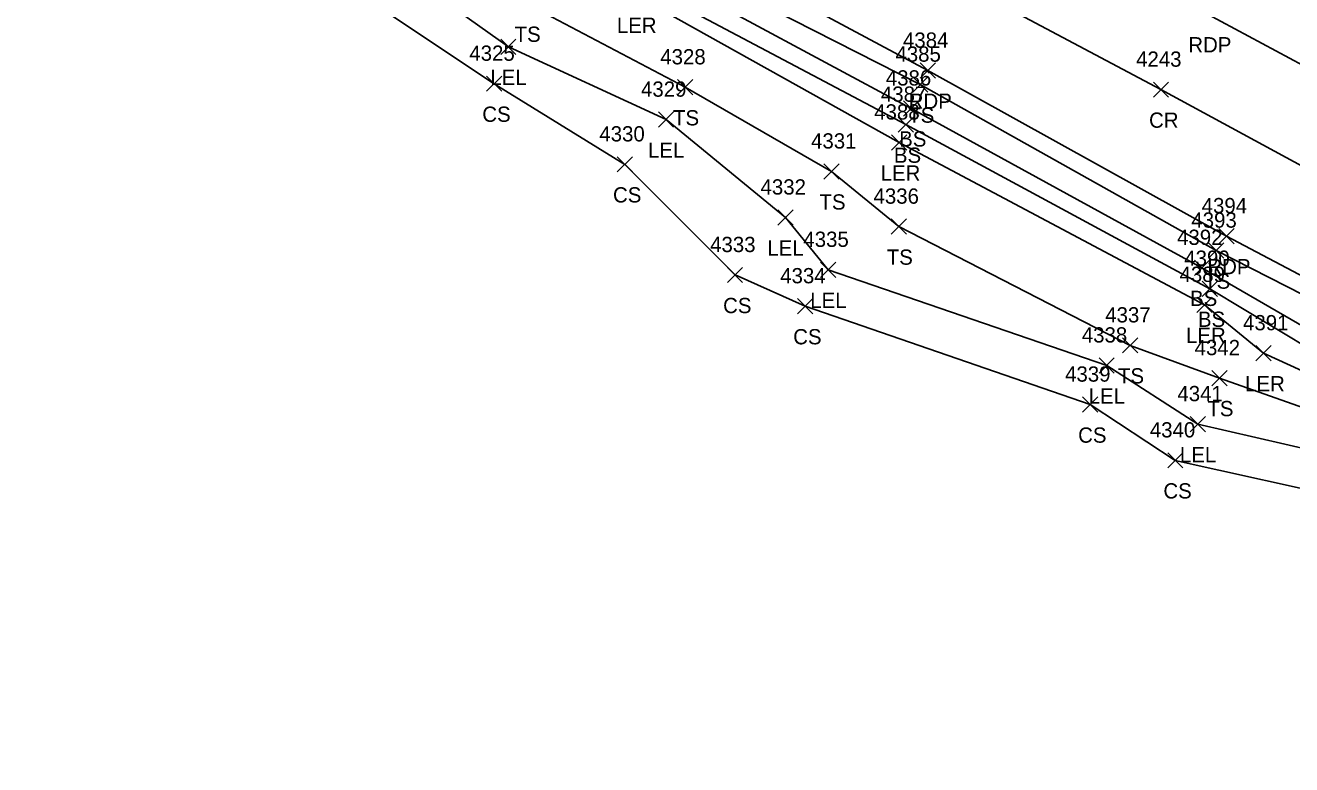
# Model space of a CAD drawing. Extents: x 1462089 to 1464015, y 730534 to 736144.
# Drawn here: x 1462373.7 to 1462539.6, y 731943.3 to 732040.2 of the extents above; entities that cross this region are included whole.
import ezdxf

# ---------------------------------------------------------------- set-up
doc = ezdxf.new("R2010")
doc.units = 0
for name, color, linetype in [('L_A', 7, 'Continuous'), ('L_I', 7, 'Continuous'), ('L_TIC', 7, 'Continuous'), ('LARO', 7, 'Continuous'), ('LELB', 7, 'Continuous'), ('P_A', 7, 'Continuous'), ('P_I', 7, 'Continuous'), ('P_TIC', 7, 'Continuous'), ('PET', 7, 'Continuous'), ('PRC', 7, 'Continuous')]:
    doc.layers.add(name, color=color, linetype=linetype)

msp = doc.modelspace()

# ---------------------------------------------------------------- linework, layer by layer
at = {"layer": 'L_TIC'}
for points in [[(1462435.98, 732036.36), (1462437.98, 732038.36)], [(1462437.98, 732036.36), (1462435.98, 732038.36)], [(1462434.13, 732031.54), (1462436.13, 732033.54)], [(1462436.13, 732031.54), (1462434.13, 732033.54)], [(1462459.14, 732031.07), (1462461.14, 732033.07)], [(1462461.14, 732031.07), (1462459.14, 732033.07)], [(1462489.94, 732031.42), (1462491.94, 732033.42)], [(1462491.94, 732031.42), (1462489.94, 732033.42)], [(1462488.73, 732028.3), (1462490.73, 732030.3)], [(1462490.73, 732028.3), (1462488.73, 732030.3)], [(1462456.63, 732026.83), (1462458.63, 732028.83)], [(1462458.63, 732026.83), (1462456.63, 732028.83)], [(1462488.04, 732026.17), (1462490.04, 732028.17)], [(1462490.04, 732026.17), (1462488.04, 732028.17)], [(1462487.16, 732023.84), (1462489.16, 732025.84)], [(1462489.16, 732023.84), (1462487.16, 732025.84)], [(1462451.25, 732020.97), (1462453.25, 732022.97)], [(1462453.25, 732020.97), (1462451.25, 732022.97)], [(1462478.32, 732020.04), (1462480.32, 732022.04)], [(1462480.32, 732020.04), (1462478.32, 732022.04)], [(1462472.27, 732014.01), (1462474.27, 732016.01)], [(1462474.27, 732014.01), (1462472.27, 732016.01)], [(1462487.13, 732012.81), (1462489.13, 732014.81)], [(1462489.13, 732012.81), (1462487.13, 732014.81)], [(1462528.7, 732009.67), (1462530.7, 732011.67)], [(1462530.7, 732009.67), (1462528.7, 732011.67)], [(1462465.67, 732006.47), (1462467.67, 732008.47)], [(1462467.67, 732006.47), (1462465.67, 732008.47)], [(1462477.88, 732007.15), (1462479.88, 732009.15)], [(1462479.88, 732007.15), (1462477.88, 732009.15)], [(1462526.83, 732007.41), (1462528.83, 732009.41)], [(1462528.83, 732007.41), (1462526.83, 732009.41)], [(1462527.86, 732004.67), (1462529.86, 732006.67)], [(1462529.86, 732004.67), (1462527.86, 732006.67)], [(1462474.85, 732002.38), (1462476.85, 732004.38)], [(1462476.85, 732002.38), (1462474.85, 732004.38)], [(1462527.16, 732002.56), (1462529.16, 732004.56)], [(1462529.16, 732002.56), (1462527.16, 732004.56)], [(1462517.42, 731997.25), (1462519.42, 731999.25)], [(1462519.42, 731997.25), (1462517.42, 731999.25)], [(1462534.9, 731996.22), (1462536.9, 731998.22)], [(1462536.9, 731996.22), (1462534.9, 731998.22)], [(1462514.35, 731994.62), (1462516.35, 731996.62)], [(1462516.35, 731994.62), (1462514.35, 731996.62)], [(1462529.13, 731992.96), (1462531.13, 731994.96)], [(1462531.13, 731992.96), (1462529.13, 731994.96)], [(1462512.17, 731989.49), (1462514.17, 731991.49)], [(1462514.17, 731989.49), (1462512.17, 731991.49)], [(1462526.3, 731986.93), (1462528.3, 731988.93)], [(1462528.3, 731986.93), (1462526.3, 731988.93)], [(1462523.34, 731982.18), (1462525.34, 731984.18)], [(1462525.34, 731982.18), (1462523.34, 731984.18)]]:
    msp.add_lwpolyline(points, dxfattribs=at)
at = {"layer": 'LARO'}
for points in [[(1462264.53, 732141.37), (1462280.8, 732137.45), (1462304.56, 732121.88), (1462332.73, 732110.49), (1462351.01, 732098.25), (1462390.86, 732077.94), (1462401.62, 732073.62), (1462407.64, 732069.31), (1462436.18, 732056.01), (1462453.6, 732044.2), (1462488.16, 732024.84), (1462528.16, 732003.56), (1462535.9, 731997.22), (1462564.82, 731983.98), (1462588.79, 731971.39), (1462609.63, 731960.71), (1462616, 731952.79), (1462625.86, 731949.03), (1462651.51, 731937.11), (1462666.81, 731928.04), (1462675.53, 731921.26)], [(1462254.75, 732128.31), (1462262.86, 732125.81), (1462285.58, 732115.58), (1462314.64, 732100.45), (1462332.44, 732090.84), (1462352.68, 732082.74), (1462381.15, 732067.23), (1462394.72, 732062.92), (1462415.67, 732052.59), (1462436.98, 732037.36), (1462457.63, 732027.83), (1462473.27, 732015.01), (1462478.88, 732008.15), (1462515.35, 731995.62), (1462527.3, 731987.93), (1462550.08, 731982.66), (1462558.92, 731973.67), (1462570.85, 731962.61), (1462577.22, 731952.72), (1462589.81, 731946.27), (1462608.55, 731942.12)]]:
    msp.add_lwpolyline(points, dxfattribs=at)
at = {"layer": 'LELB'}
for points in [[(1462268.94, 732149.28), (1462308.43, 732128.71), (1462354.33, 732103.89), (1462394.15, 732084.39), (1462412.36, 732075.22), (1462457.64, 732049.36), (1462490.94, 732032.42), (1462529.7, 732010.67), (1462568.83, 731990.73), (1462593.62, 731976.79), (1462623.59, 731960), (1462654.37, 731942.73), (1462672.05, 731932.37), (1462692.12, 731920.93), (1462699.46, 731912.9)], [(1462266.76, 732145.23), (1462282.11, 732139.32), (1462308.3, 732126.23), (1462353.11, 732101.19), (1462392.77, 732082.13), (1462410, 732072.54), (1462437.81, 732058.16), (1462456.1, 732047.42), (1462489.73, 732029.3), (1462527.83, 732008.41), (1462565.4, 731986.64), (1462591.35, 731974.35), (1462620.09, 731957.41), (1462653.18, 731940.63), (1462669.35, 731930.26), (1462687.58, 731918.81), (1462686.57, 731917.12)], [(1462265.41, 732143.18), (1462280.8, 732137.45), (1462306.42, 732125.03), (1462332.73, 732110.49), (1462352.67, 732099.71), (1462392.05, 732079.23), (1462401.62, 732073.62), (1462408.5, 732070.13), (1462436.18, 732056.01), (1462454.76, 732045.38), (1462489.04, 732027.17), (1462528.86, 732005.67), (1462564.82, 731983.98), (1462590.19, 731972.53), (1462609.63, 731960.71), (1462619.8, 731955.25), (1462652.26, 731939.11), (1462668.15, 731929.16), (1462686.57, 731917.12)], [(1462259.38, 732133.38), (1462264.6, 732131.81), (1462288.8, 732120.32), (1462319.43, 732102.58), (1462334.48, 732096.72), (1462355.6, 732085.94), (1462385.9, 732070.37), (1462398.62, 732070.04), (1462418.37, 732059.41), (1462439.39, 732043.02), (1462460.14, 732032.07), (1462479.32, 732021.04), (1462488.13, 732013.81), (1462518.42, 731998.25), (1462530.13, 731993.96), (1462552.89, 731985.91), (1462561.32, 731977.65), (1462577.83, 731967.62), (1462595.47, 731955.47), (1462607.49, 731949.55), (1462608.2, 731946.49), (1462648.04, 731929.15)], [(1462251.41, 732121.51), (1462260.34, 732120.37), (1462283.18, 732109.04), (1462310.5, 732093.66), (1462326.84, 732085.72), (1462347.54, 732077.16), (1462380.03, 732062.41), (1462392.14, 732057.7), (1462410.67, 732048.85), (1462435.13, 732032.54), (1462452.25, 732021.97), (1462466.67, 732007.47), (1462475.85, 732003.38), (1462513.17, 731990.49), (1462524.34, 731983.18), (1462547.61, 731978.02), (1462566.75, 731959.76), (1462577.22, 731952.72), (1462603.04, 731935.03)]]:
    msp.add_lwpolyline(points, dxfattribs=at)
at = {"layer": 'P_TIC'}
for points in [[(1462490.93, 732033.25), (1462492.93, 732035.25)], [(1462492.93, 732033.25), (1462490.93, 732035.25)], [(1462521.46, 732030.76), (1462523.46, 732032.76)], [(1462523.46, 732030.76), (1462521.46, 732032.76)], [(1462530.05, 732011.56), (1462532.05, 732013.56)], [(1462532.05, 732011.56), (1462530.05, 732013.56)]]:
    msp.add_lwpolyline(points, dxfattribs=at)
at = {"layer": 'PET'}
for points in [[(1462744.84, 731999.27), (1462742.33, 731993.22), (1462735.48, 731981.56), (1462730.64, 731976.02), (1462728.98, 731974.4), (1462721.4, 731968.23), (1462710.52, 731963.39), (1462695.09, 731960.11), (1462681.48, 731960.8), (1462668.27, 731966.22), (1462638.36, 731982.5), (1462604.11, 732001.12), (1462569.71, 732019.56), (1462528.56, 732041.64), (1462492.34, 732061.31), (1462453.18, 732082.82), (1462423.34, 732099.23), (1462387.22, 732118.93), (1462352.22, 732137.53), (1462321.66, 732153.59), (1462281.35, 732173.27)], [(1462270.45, 732152.1), (1462310.22, 732132.27), (1462357.01, 732107.8), (1462395.93, 732087.15), (1462413.05, 732077.52), (1462458.62, 732052.14), (1462491.93, 732034.25), (1462531.05, 732012.56), (1462569.66, 731992.17), (1462594.88, 731978.54), (1462624.97, 731962.02), (1462656.05, 731945.2), (1462673.71, 731935.25), (1462698.16, 731921.06), (1462701.54, 731917.94), (1462703.76, 731916.18), (1462713.41, 731906.91), (1462715.89, 731903.55), (1462716.95, 731899.27), (1462716.13, 731895.69)]]:
    msp.add_lwpolyline(points, dxfattribs=at)
at = {"layer": 'PRC'}
msp.add_lwpolyline([(1462724.35, 731923.62), (1462700.47, 731936.6), (1462662.88, 731956.21), (1462633.35, 731971.36), (1462598.49, 731991.21), (1462563, 732009.78), (1462522.46, 732031.76), (1462486.74, 732050.76), (1462447.61, 732072.43), (1462416.62, 732089.42), (1462381.13, 732108.67), (1462345.7, 732127.48), (1462314.56, 732143.61), (1462276.11, 732162.81)], dxfattribs=at)

# ---------------------------------------------------------------- texts
at = {"layer": 'L_A'}
for s, p in [('LER', (1462451.19, 732039.2)), ('TS', (1462437.8, 732038.02)), ('LEL', (1462434.62, 732032.36)), ('CS', (1462433.57, 732027.54)), ('TS', (1462458.55, 732027.07)), ('TS', (1462489.35, 732027.42)), ('BS', (1462488.17, 732024.3)), ('LEL', (1462455.27, 732022.83)), ('BS', (1462487.48, 732022.17)), ('LER', (1462485.74, 732019.84)), ('CS', (1462450.69, 732016.97)), ('TS', (1462477.73, 732016.04)), ('LEL', (1462470.91, 732010.01)), ('TS', (1462486.54, 732008.81)), ('TS', (1462528.11, 732005.67)), ('LEL', (1462476.52, 732003.15)), ('BS', (1462526.27, 732003.41)), ('CS', (1462465.11, 732002.47)), ('BS', (1462527.3, 732000.67)), ('CS', (1462474.29, 731998.38)), ('LER', (1462525.74, 731998.56)), ('TS', (1462516.83, 731993.25)), ('LER', (1462533.48, 731992.22)), ('LEL', (1462512.99, 731990.62)), ('TS', (1462528.54, 731988.96)), ('CS', (1462511.61, 731985.49)), ('LEL', (1462524.94, 731982.93)), ('CS', (1462522.78, 731978.18))]:
    msp.add_text(s, height=2, dxfattribs=at).set_placement(p)
at = {"layer": 'L_I'}
for s, p in [('4325', (1462431.87, 732035.54)), ('4328', (1462456.88, 732035.07)), ('4385', (1462487.68, 732035.42)), ('4329', (1462454.36, 732030.83)), ('4386', (1462486.42, 732032.3)), ('4387', (1462485.78, 732030.17)), ('4388', (1462484.9, 732027.84)), ('4330', (1462448.9, 732024.97)), ('4331', (1462476.63, 732024.04)), ('4332', (1462470.01, 732018.01)), ('4336', (1462484.81, 732016.81)), ('4393', (1462526.44, 732013.67)), ('4335', (1462475.62, 732011.15)), ('4392', (1462524.57, 732011.41)), ('4333', (1462463.41, 732010.47)), ('4390', (1462525.51, 732008.67)), ('4334', (1462472.59, 732006.38)), ('4389', (1462524.89, 732006.56)), ('4337', (1462515.16, 732001.25)), ('4391', (1462533.21, 732000.22)), ('4338', (1462512.09, 731998.62)), ('4342', (1462526.87, 731996.96)), ('4339', (1462509.9, 731993.49)), ('4341', (1462524.61, 731990.93)), ('4340', (1462521, 731986.18))]:
    msp.add_text(s, height=2, dxfattribs=at).set_placement(p)
at = {"layer": 'P_A'}
for s, p in [('RDP', (1462526.04, 732036.64)), ('RDP', (1462489.42, 732029.25)), ('CR', (1462520.9, 732026.76)), ('RDP', (1462528.54, 732007.56))]:
    msp.add_text(s, height=2, dxfattribs=at).set_placement(p)
at = {"layer": 'P_I'}
for s, p in [('4384', (1462488.67, 732037.25)), ('4243', (1462519.2, 732034.76)), ('4394', (1462527.79, 732015.56))]:
    msp.add_text(s, height=2, dxfattribs=at).set_placement(p)

doc.saveas('drawing.dxf')
